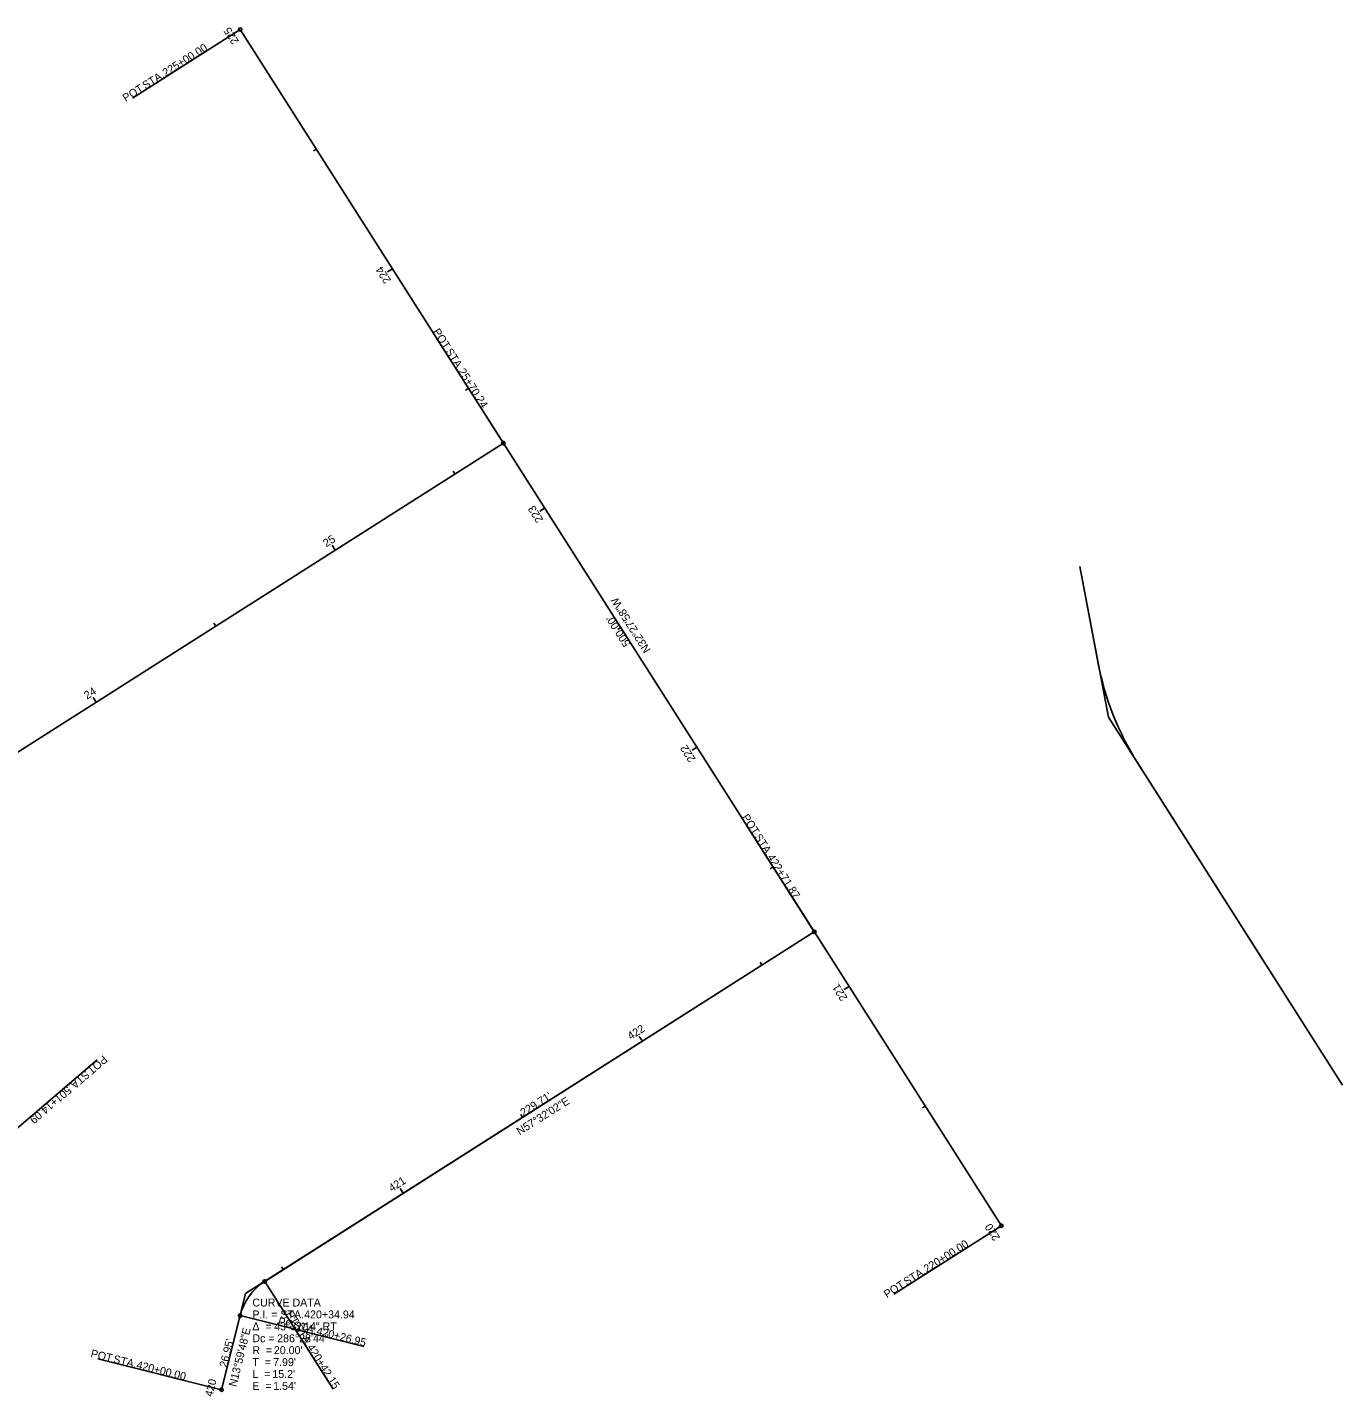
# Model space of a CAD drawing. Extents: x 144966 to 145878, y 513593 to 514347.
# Drawn here: x 145414 to 145877.8, y 513864.2 to 514347.1 of the extents above; entities that cross this region are included whole.
import ezdxf

# ---------------------------------------------------------------- set-up
doc = ezdxf.new("R2010")
doc.units = 0
for name, color, linetype in [('_CIVIL_CONSTRUCTION', 7, 'Continuous'), ('GE_P_Alignment_100_Bearings', 7, 'Continuous'), ('GE_P_Alignment_100_Cardinal_Points', 7, 'Continuous'), ('GE_P_Alignment_100_Curve_Data', 7, 'Continuous'), ('GE_P_Alignment_100_Distances', 7, 'Continuous'), ('GE_P_Alignment_100_Stations', 7, 'Continuous'), ('GE_P_Driveway_CL', 7, 'Continuous'), ('PV_P_Curb', 7, 'Continuous')]:
    doc.layers.add(name, color=color, linetype=linetype)

msp = doc.modelspace()

# ---------------------------------------------------------------- linework, layer by layer
at = {"layer": '_CIVIL_CONSTRUCTION'}
for p, q in [((145785.18, 514156.99), (145795.23, 514103.84)), ((145795.23, 514103.84), (145877.8, 513974.06)), ((145490.96, 513900.52), (145691.51, 514028.12)), ((145482.51, 513866.62), (145490.96, 513900.52))]:
    msp.add_line(p, q, dxfattribs=at)
for centre, radius, start, end in [((145889.91, 514141.31), 100, 190.7095, 212.4662), ((145508.43, 513887.94), 20, 122.4662, 166.0034)]:
    msp.add_arc(centre, radius, start, end, dxfattribs=at)
at = {"layer": 'GE_P_Alignment_100_Bearings'}
for p, q in [((145757.46, 513924.47), (145489.06, 514346.32)), ((145100.75, 513894.34), (145581.86, 514200.45)), ((145497.7, 513904.81), (145691.51, 514028.12)), ((145482.51, 513866.62), (145489.03, 513892.77))]:
    msp.add_line(p, q, dxfattribs=at)
msp.add_arc((145508.43, 513887.94), 20, 122.4662, 166.0034, dxfattribs=at)
at = {"layer": 'GE_P_Alignment_100_Curve_Data'}
for p, q in [((145489.06, 514346.32), (145451.09, 514322.16)), ((145581.86, 514200.45), (145557.71, 514238.42)), ((145691.51, 514028.12), (145667.35, 514066.09)), ((145404.43, 513953.69), (145438.61, 513982.96)), ((145757.46, 513924.47), (145719.49, 513900.31)), ((145497.7, 513904.81), (145521.85, 513866.84)), ((145489.03, 513892.77), (145532.69, 513881.89)), ((145482.51, 513866.62), (145438.84, 513877.5))]:
    msp.add_line(p, q, dxfattribs=at)
for centre in [(145489.06, 514346.32), (145581.86, 514200.45), (145691.51, 514028.12), (145757.46, 513924.47), (145497.7, 513904.81), (145489.03, 513892.77), (145482.51, 513866.62)]:
    msp.add_circle(centre, 0.6, dxfattribs=at)
at = {"layer": 'GE_P_Alignment_100_Stations'}
for p, q in [((145489.06, 514346.32), (145487.37, 514345.25)), ((145515.9, 514304.13), (145514.88, 514303.49)), ((145542.74, 514261.95), (145541.05, 514260.88)), ((145569.58, 514219.76), (145568.56, 514219.12)), ((145564.79, 514189.58), (145564.14, 514190.6)), ((145596.42, 514177.58), (145594.73, 514176.5)), ((145522.6, 514162.74), (145521.53, 514164.43)), ((145480.42, 514135.9), (145479.77, 514136.92)), ((145623.26, 514135.39), (145622.24, 514134.75)), ((145438.23, 514109.06), (145437.16, 514110.75)), ((145650.1, 514093.21), (145648.41, 514092.13)), ((145676.94, 514051.02), (145675.92, 514050.38)), ((145673.06, 514016.38), (145672.41, 514017.4)), ((145703.78, 514008.84), (145702.09, 514007.76)), ((145630.87, 513989.54), (145629.8, 513991.23)), ((145730.62, 513966.65), (145729.61, 513966.01)), ((145588.69, 513962.7), (145588.04, 513963.72)), ((145546.5, 513935.86), (145545.43, 513937.55)), ((145757.46, 513924.47), (145755.77, 513923.39)), ((145504.32, 513909.02), (145503.67, 513910.03)), ((145482.51, 513866.62), (145480.57, 513867.1))]:
    msp.add_line(p, q, dxfattribs=at)
at = {"layer": 'GE_P_Driveway_CL'}
for p, q in [((145785.18, 514156.99), (145791.65, 514122.73)), ((145805.54, 514087.63), (145877.8, 513974.06))]:
    msp.add_line(p, q, dxfattribs=at)
msp.add_arc((145889.91, 514141.31), 100, 190.7095, 212.4662, dxfattribs=at)

# ---------------------------------------------------------------- texts
at = {"layer": 'GE_P_Alignment_100_Cardinal_Points'}
for s, rotation, p in [('N32°27\'58"W', 122.4662, (145633.92, 514127.58)), ('N57°32\'02"E', 32.4662, (145587.59, 513956.32)), ('N13°59\'48"E', 76.0034, (145487.67, 513867.51))]:
    msp.add_text(s, height=2.8, rotation=rotation, dxfattribs=at).set_placement(p)
at = {"layer": 'GE_P_Alignment_100_Curve_Data'}
for s, rotation, p in [('225+00.00', 32.4662, (145462.76, 514329.64)), ('POT', 32.4662, (145448.71, 514320.7)), (' STA. ', 32.4662, (145454.78, 514324.56)), ('POT', 302.4662, (145556.88, 514239.8)), (' STA. ', 302.4662, (145560.75, 514233.72)), ('25+70.24', 302.4662, (145565.82, 514225.75)), ('POT', 302.4662, (145665.85, 514068.53)), (' STA. ', 302.4662, (145669.71, 514062.46)), ('422+71.87', 302.4662, (145674.79, 514054.48)), ('POT', 220.5819, (145440.74, 513984.73)), (' STA. ', 220.5819, (145435.27, 513980.05)), ('501+14.09', 220.5819, (145428.09, 513973.9)), ('220+00.00', 32.4662, (145731.16, 513907.78)), (' STA. ', 32.4662, (145723.18, 513902.71)), ('POT', 32.4662, (145717.11, 513898.84)), ('PT', 302.4662, (145505.05, 513893.33)), ('PC', 346.0034, (145502.18, 513889.54)), (' STA. ', 346.0034, (145506.63, 513888.43)), (' STA. ', 302.4662, (145507.42, 513889.6)), ('420+26.95', 346.0034, (145515.8, 513886.14)), ('POT', 346.0034, (145436.14, 513878.22)), (' STA. ', 346.0034, (145443.12, 513876.48)), ('420+42.15', 302.4662, (145512.49, 513881.63)), ('420+00.00', 346.0034, (145452.29, 513874.19))]:
    msp.add_text(s, height=2.8, rotation=rotation, dxfattribs=at).set_placement(p)
at = {"layer": 'GE_P_Alignment_100_Distances'}
for s, rotation, p in [("500.00'", 122.4662, (145626.81, 514129.73)), ("229.71'", 32.4662, (145588.94, 513962.92)), ("26.95'", 76.0034, (145484.38, 513874.31))]:
    msp.add_text(s, height=2.8, rotation=rotation, dxfattribs=at).set_placement(p)
at = {"layer": 'GE_P_Alignment_100_Stations'}
for s, rotation, p in [('225', 122.4662, (145488.72, 514342.19)), ('224', 122.4662, (145542.38, 514257.85)), ('223', 122.4662, (145596.06, 514173.48)), ('25', 32.4662, (145519.41, 514163.68)), ('24', 32.4662, (145435.07, 514110.02)), ('222', 122.4662, (145649.75, 514089.1)), ('221', 122.4662, (145703.36, 514004.84)), ('422', 32.4662, (145626.76, 513989.89)), ('421', 32.4662, (145542.5, 513936.28)), ('220', 122.4662, (145757.14, 513920.3)), ('420', 76.0034, (145479.27, 513863.98))]:
    msp.add_text(s, height=2.8, rotation=rotation, dxfattribs=at).set_placement(p)
at = {"layer": 'PV_P_Curb'}
for s, p in [('CURVE DATA', (145493.36, 513895.99)), ('P.I. = STA. ', (145493.36, 513891.79)), ('420+34.94', (145511.63, 513891.79)), ('Δ  = ', (145493.36, 513887.59)), ('43°32\'14" RT', (145501.04, 513887.59)), ('Dc = ', (145493.36, 513883.39)), ('286°28\'44"', (145502.1, 513883.39)), ('R  = ', (145493.36, 513879.19)), ("20.00'", (145500.94, 513879.19)), ('T  = ', (145493.36, 513874.99)), ('L  = ', (145493.36, 513870.79)), ("15.2'", (145500.4, 513870.79)), ("7.99'", (145500.7, 513874.99)), ('E  = ', (145493.36, 513866.59)), ("1.54'", (145500.7, 513866.59))]:
    msp.add_text(s, height=2.8, dxfattribs=at).set_placement(p)

doc.saveas('drawing.dxf')
